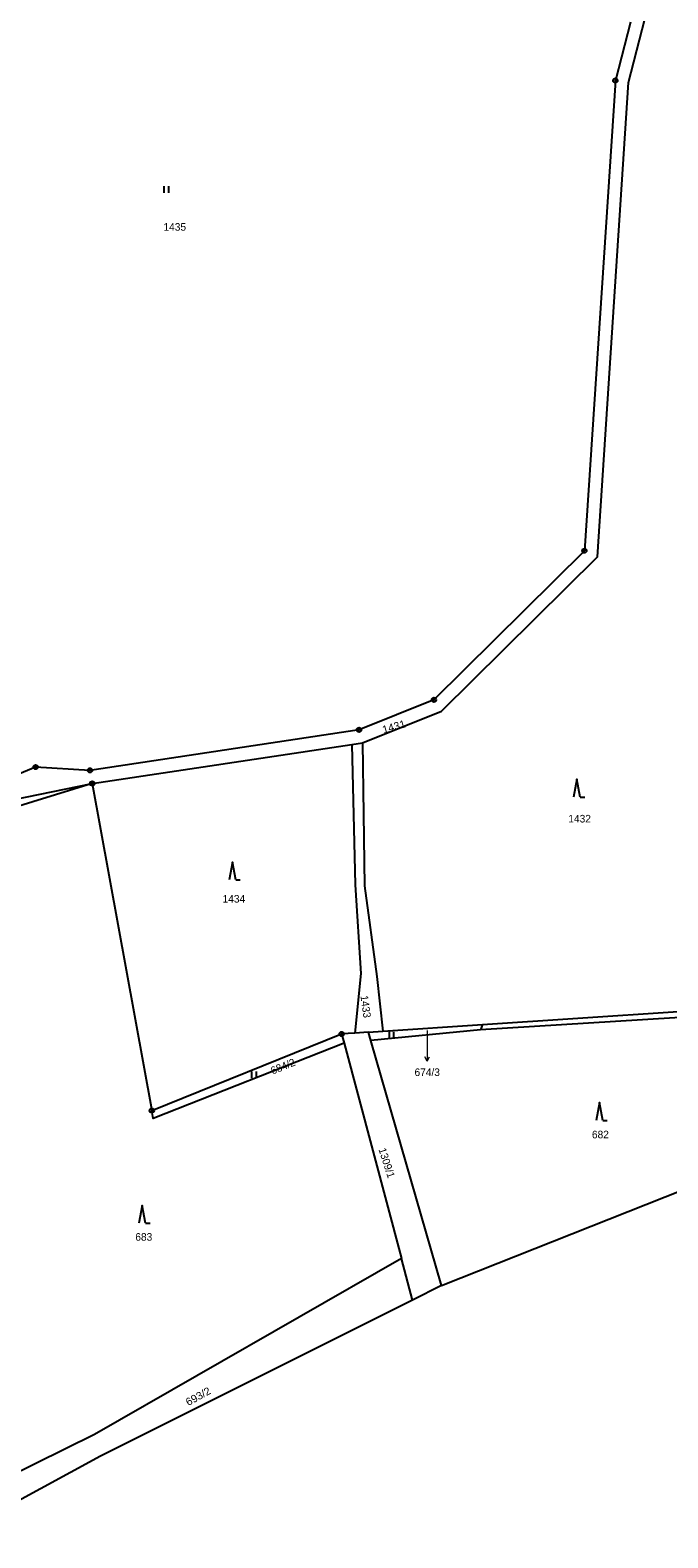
# Model space of a CAD drawing. Extents: x -872229 to -869198, y -1075981 to -1074329.
# Drawn here: x -870632.3 to -870489.5, y -1075924.5 to -1075586.7 of the extents above; entities that cross this region are included whole.
import ezdxf
from ezdxf.enums import TextEntityAlignment as Align

# ---------------------------------------------------------------- set-up
doc = ezdxf.new("R2010")
doc.units = 0
doc.header["$LTSCALE"] = 0.68
for name, color, linetype, lineweight in [('1', 7, 'Continuous', 25), ('3', 7, 'Continuous', 25), ('7', 7, 'Continuous', 13), ('8', 7, 'Continuous', 25)]:
    doc.layers.add(name, color=color, linetype=linetype, lineweight=lineweight)
doc.layers.add('2', color=7, linetype='Continuous')

msp = doc.modelspace()

# ---------------------------------------------------------------- linework, layer by layer
at = {"layer": '1'}
for p, q in [((-870618.4, -1075755.49), (-870650.51, -1075765.39)), ((-870618.4, -1075755.49), (-870605.06, -1075828.76)), ((-870605.06, -1075828.76), (-870562.55, -1075811.59)), ((-870556.56, -1075811.18), (-870553.35, -1075810.97)), ((-870531.01, -1075809.47), (-870531.41, -1075810.63)), ((-870540.14, -1075867.94), (-870556.01, -1075813.08)), ((-870540.14, -1075867.94), (-870448.9, -1075831.7)), ((-870546.66, -1075871.21), (-870549.14, -1075861.93)), ((-870540.14, -1075867.94), (-870546.66, -1075871.21))]:
    msp.add_line(p, q, dxfattribs=at)
for points in [[(-870557.85, -1075746.37), (-870540.19, -1075739.3), (-870505.25, -1075704.66), (-870498.26, -1075598.45), (-870480.43, -1075529.12)], [(-870497.88, -1075584.92), (-870501.24, -1075597.99), (-870508.17, -1075703.33), (-870541.87, -1075736.74), (-870558.64, -1075743.46), (-870618.91, -1075752.53), (-870631.08, -1075751.8), (-870646.39, -1075758.16), (-870662.6, -1075767.96)], [(-870531.01, -1075809.47), (-870465.83, -1075805.11), (-870466.06, -1075737.62), (-870469.57, -1075719.09)], [(-870650.51, -1075765.39), (-870645.07, -1075760.95), (-870618.4, -1075755.49), (-870560.25, -1075746.77), (-870557.85, -1075746.37)], [(-870560.25, -1075746.77), (-870559.51, -1075778.18), (-870558.26, -1075798.03), (-870559.56, -1075811.39)], [(-870557.85, -1075746.37), (-870557.65, -1075762.37), (-870557.39, -1075778.39), (-870554.62, -1075798.71), (-870553.35, -1075810.97), (-870531.01, -1075809.47)], [(-870457.7, -1075806.11), (-870531.41, -1075810.63), (-870556.01, -1075813.08)], [(-870556.01, -1075813.08), (-870556.56, -1075811.18), (-870559.56, -1075811.39), (-870562.55, -1075811.59), (-870562, -1075813.65), (-870549.14, -1075861.93)], [(-870562, -1075813.65), (-870604.75, -1075830.51), (-870605.06, -1075828.76)], [(-870549.14, -1075861.93), (-870617.86, -1075901.31), (-870650.72, -1075917.52)], [(-870546.66, -1075871.21), (-870616.52, -1075906.2), (-870650.23, -1075924.48)]]:
    msp.add_lwpolyline(points, dxfattribs=at)
at = {"layer": '3'}
for p, q in [((-870602.251, -1075623.14), (-870602.251, -1075621.64)), ((-870601.25, -1075623.14), (-870601.25, -1075621.64)), ((-870509.08, -1075758.53), (-870508.084, -1075758.53)), ((-870586.25, -1075777.09), (-870585.254, -1075777.09)), ((-870551.821, -1075812.59), (-870551.821, -1075811.09)), ((-870550.82, -1075812.59), (-870550.82, -1075811.09)), ((-870582.621, -1075821.53), (-870582.621, -1075820.03)), ((-870581.62, -1075821.53), (-870581.62, -1075820.03)), ((-870504.06, -1075830.98), (-870503.064, -1075830.98)), ((-870606.45, -1075853.99), (-870605.454, -1075853.99))]:
    msp.add_line(p, q, dxfattribs=at)
for points in [[(-870509.08, -1075758.53), (-870509.83, -1075754.53), (-870510.58, -1075758.53)], [(-870586.25, -1075777.09), (-870587, -1075773.09), (-870587.75, -1075777.09)], [(-870504.06, -1075830.98), (-870504.81, -1075826.98), (-870505.56, -1075830.98)], [(-870606.45, -1075853.99), (-870607.2, -1075849.99), (-870607.95, -1075853.99)]]:
    msp.add_lwpolyline(points, dxfattribs=at)
at = {"layer": '7'}
msp.add_line((-870543.37, -1075817.711), (-870542.869, -1075816.71), dxfattribs=at)
msp.add_lwpolyline([(-870543.37, -1075810.85), (-870543.37, -1075814.71), (-870543.37, -1075817.711), (-870543.871, -1075816.71)], dxfattribs=at)
at = {"layer": '8'}
for centre, radius in [((-870501.24, -1075597.9899), 0.5), ((-870501.24, -1075597.9899), 0.0303), ((-870508.17, -1075703.3299), 0.5), ((-870508.17, -1075703.3299), 0.0303), ((-870541.87, -1075736.7399), 0.5), ((-870541.87, -1075736.7399), 0.0303), ((-870558.64, -1075743.4599), 0.5), ((-870558.64, -1075743.4599), 0.0303), ((-870631.08, -1075751.7999), 0.5), ((-870631.08, -1075751.7999), 0.0303), ((-870618.91, -1075752.5299), 0.5), ((-870618.91, -1075752.5299), 0.0303), ((-870618.4, -1075755.4899), 0.5), ((-870618.4, -1075755.4899), 0.0303), ((-870562.55, -1075811.5899), 0.5), ((-870562.55, -1075811.5899), 0.0303), ((-870605.06, -1075828.7599), 0.5), ((-870605.06, -1075828.7599), 0.0303)]:
    msp.add_circle(centre, radius, dxfattribs=at)

# ---------------------------------------------------------------- texts
at = {"layer": '2'}
for s, p in [('1435', (-870602.44, -1075631.63)), ('1432', (-870511.77, -1075764.21)), ('1434', (-870589.2, -1075782.16)), ('682', (-870506.48, -1075834.97)), ('683', (-870608.75, -1075857.91))]:
    msp.add_text(s, height=1.7, dxfattribs=at).set_placement(p)
at = {"layer": '2', "width": 1.05}
for s, rotation, p in [('1431', 16, (-870553.155, -1075744.297)), ('693/2', 29, (-870596.877, -1075894.973))]:
    msp.add_text(s, height=1.7, rotation=rotation, dxfattribs=at).set_placement(p)
at = {"layer": '2'}
for s, rotation, p in [('1433', 278, (-870558.331, -1075803.068)), ('684/2', 22, (-870578.001, -1075820.708)), ('1309/1', 288, (-870554.308, -1075837.432))]:
    msp.add_text(s, height=1.7, rotation=rotation, dxfattribs=at).set_placement(p)
msp.add_text('674/3', height=1.7, dxfattribs=at).set_placement((-870543.37, -1075821.01), align=Align.CENTER)

doc.saveas('drawing.dxf')
